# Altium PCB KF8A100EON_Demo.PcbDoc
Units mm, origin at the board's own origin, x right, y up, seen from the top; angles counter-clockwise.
Board outline 55.05 x 80.01 mm, 2 copper layers (Top Layer, Bottom Layer); 33 components, 41 nets, 150 pads, 19 vias.
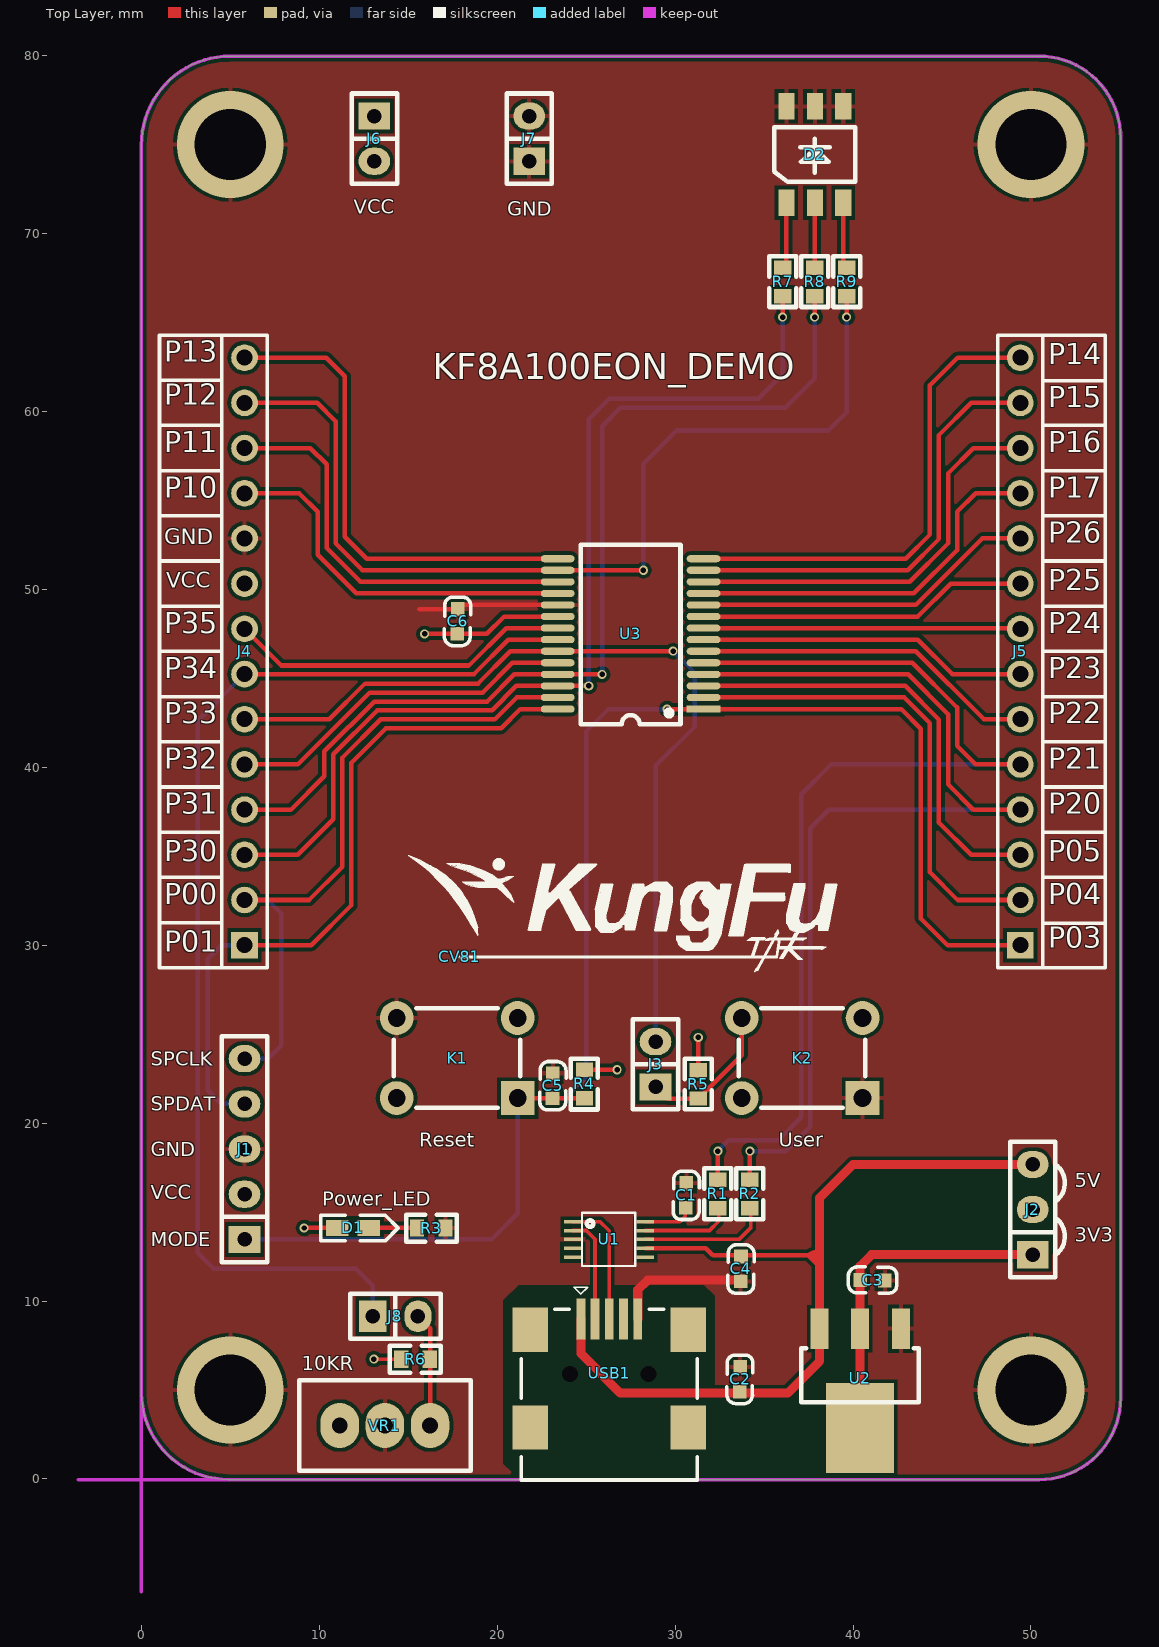
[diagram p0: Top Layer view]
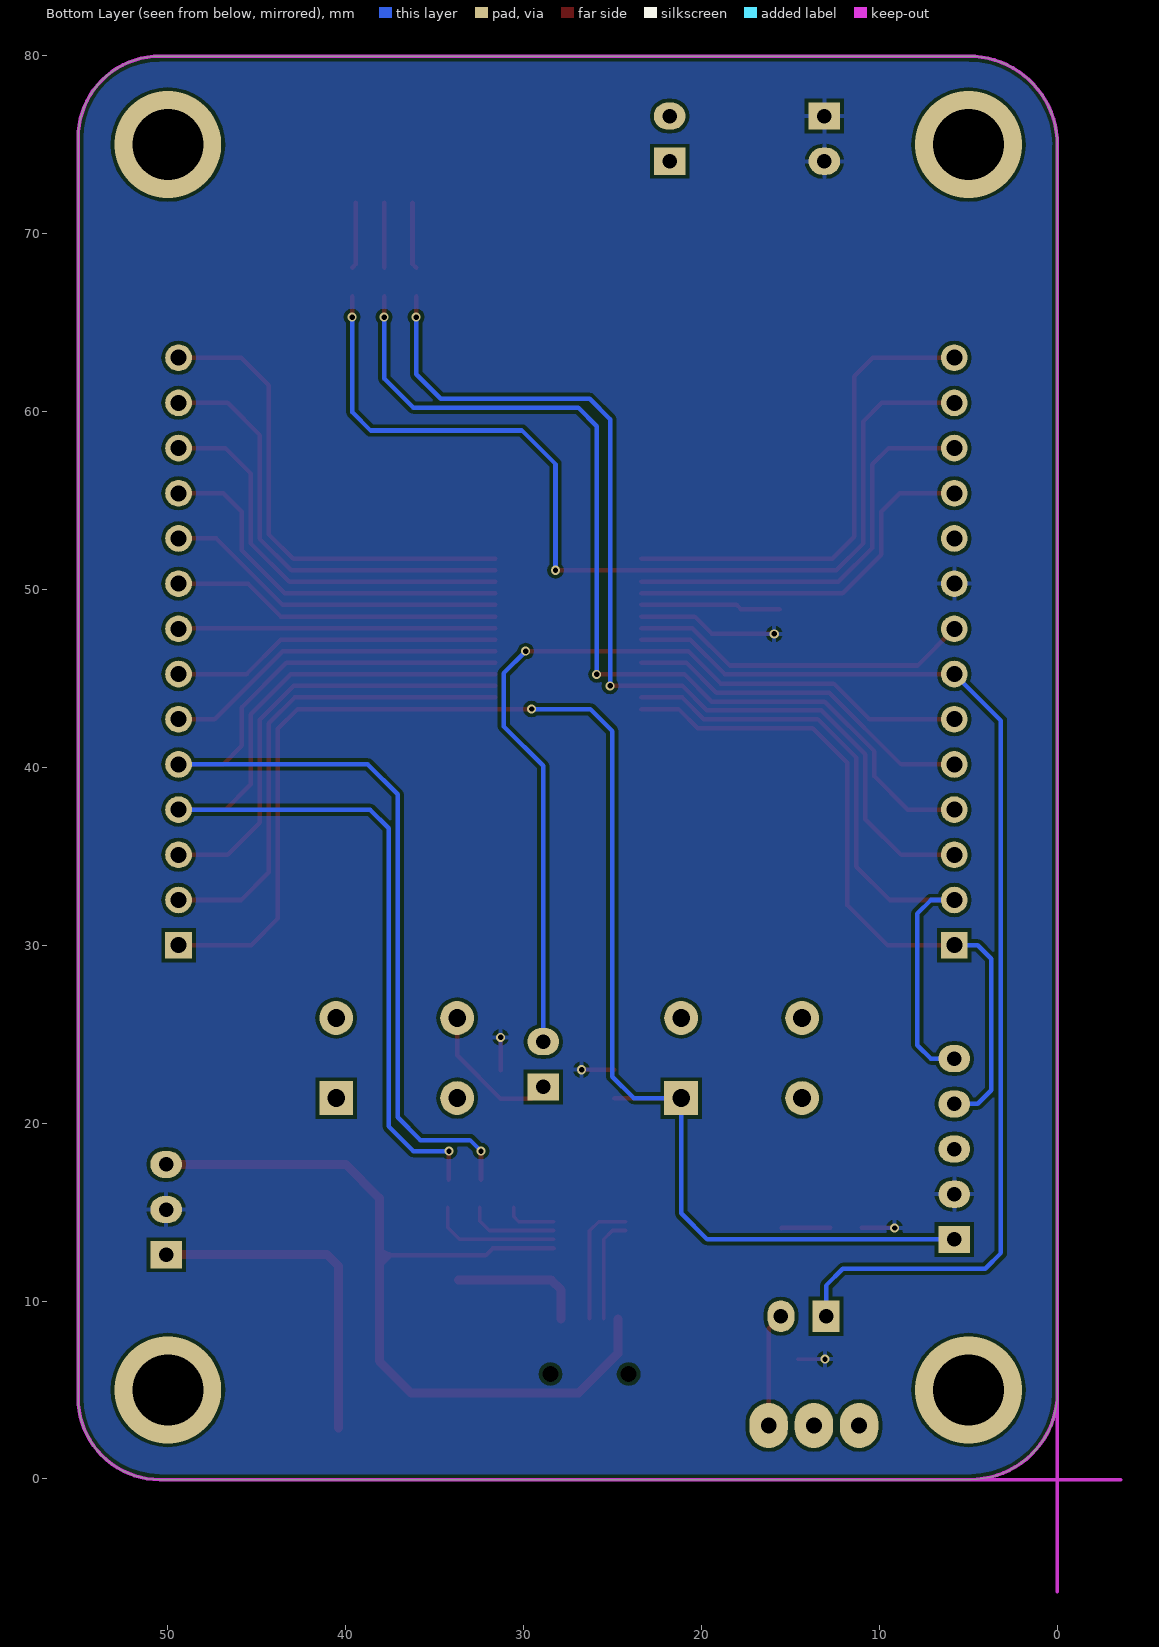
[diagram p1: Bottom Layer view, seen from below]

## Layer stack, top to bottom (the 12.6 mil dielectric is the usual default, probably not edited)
Top Layer: signal copper 0.0356
Dielectric: dielectric 0.32, FR-4, Dk 4.8
Bottom Layer: signal copper 0.0356

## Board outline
4.906,-0.034 cw(c4.906,4.873) 0,4.826 0,74.973 cw(c5,74.973) 5,79.973 50.443,79.973 cw(c50.443,75.369) 55.047,75.369 55.045,75.369 55.039,4.547 55.041,4.547 cw(c50.46,4.547) 50.46,-0.034

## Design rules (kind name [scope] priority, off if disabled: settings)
Clearance [All] p1: gap=0.203
HoleSize [All] p1: absolutevalues=TRUE maxlimit=4 minlimit=0.025 maxpercent=80.000 minpercent=20.000
PolygonConnect [All] p1: connectstyle=Relief reliefconductorwidth=0.254 reliefentries=4 polygonreliefangle="90 Angle"
RoutingVias [All] p1: holewidth=0.711 width=1.27 viastyle="Through Hole" minholewidth=0.305 minwidth=0.508 maxholewidth=4 maxwidth=6
SolderMaskExpansion [All] p1: expansion=0.102
TestPointUsage [All] p1: valid=0 allowmultiple=FALSE
Testpoint [All] p1: side=15 testpointundercomponent=TRUE minsize=1.016 maxsize=2.54 preferedsize=1.524 minholesize=0 maxholesize=1.016 preferedholesize=0.813 testpointgrid=0.025 style=1023 order=0-112345678
Width [All] p1: maxlimit=0.762 minlimit=0.203 preferedwidth=0.254
18 further rules are at their usual default settings.

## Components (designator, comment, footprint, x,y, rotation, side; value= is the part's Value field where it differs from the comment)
C1 "0.1uF" 0603C 30.6,15.238 r90 top
C2 "22uF" 0603C 33.67,6.3 r270 top
C3 "10uF" 0603C 41.8,11.146 r180 top
C4 "10nF" 0603C 33.67,11.1 r90 top
C5 "100nF" 0603C 23.1,21.4 r90 top
C6 "100nF" 0603C 17.8,48.9 r270 top
CV81 "Comment" LOGO 17.907,29.337 r0 top
D1 "LED" LED-0603B 11,14.1 r0 top
D2 "LED-5050" LED-5050W 36.2,71.773 r90 top
J1 "DEBUG" "Pin HDR1X5/2.54mm-S" 5.8,13.462 r180 top locked
J2 "Pin HDR1X3" "Pin HDR1X3/2.54mm-S" 50.1,12.6 r180 top
J3 "Pin HDR1X2" "Pin HDR1X2/2.54mm-S" 28.901,22.037 r180 top
J4 "Pin HDR1X14" "Pin HDR1X14/2.54mm-S" 5.8,30 r90 top
J5 "Pin HDR1X14" "Pin HDR1X14/2.54mm-S" 49.4,30 r90 top locked
J6 "Pin HDR1X2" "Pin HDR1X2/2.54mm-S" 13.1,76.6 r0 top
J7 "Pin HDR1X2" "Pin HDR1X2/2.54mm-S" 21.8,74.06 r180 top
J8 "Pin HDR1X2" "Pin HDR1X2/2.54mm-S" 13.006,9.144 r90 top
K1 "KEY" DIP-6X6X4.3 21.151,21.408 r180 top
K2 "KEY" DIP-6X6X4.3 40.541,21.408 r180 top
R1 "300R" 0603R 32.4,16.818 r270 top
R2 "300R" 0603R 34.2,16.818 r270 top
R3 "470R" 0603R 17.1,14.1 r180 top
R4 "10K" 0603R 24.9,21.4 r90 top
R5 "10K" 0603R 31.301,22.977 r270 top
R6 "10K" 0603R 14.606,6.731 r0 top
R7 "300R" 0603R 36.046,68.079 r270 top
R8 "300R" 0603R 37.846,68.079 r270 top
R9 "300R" 0603R 39.646,68.079 r270 top
U1 "CH340E" MSOP10 24.257,13.462 r0 top
U2 "AMS1117" SOT223 40.4,8.45 r180 top
U3 "KF8FA100EON" SSOP28 27.5,47.498 r180 top locked
USB1 "MINI-USB" USB-MINI-A 24.7,9 r0 top
VR1 "10K" 3296W 13.69,3 r0 top

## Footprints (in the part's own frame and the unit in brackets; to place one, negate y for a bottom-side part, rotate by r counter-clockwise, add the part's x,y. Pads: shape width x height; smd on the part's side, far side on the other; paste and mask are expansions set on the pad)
0603C [mil]
  rect 30x30 smd: 1(0.21,-0.35) 2(55.21,-1.35)
  silkscreen extent -26,-30 81,28, body extent -1,-15 62,17, height 12
0603R [mm]
  rect 0.8x0.965 smd: 1(0,0) 2(1.6,0)
  silkscreen extent -0.64,-0.76 2.21,0.76, body extent -0.04,-0.41 1.56,0.41, height 0.45
3296W [mil]
  oval 85x100 hole 35: 1(-100,0) 2(0,0) 3(100,0)
  silkscreen extent -190,-100 190,100, body extent -188,-94 188,94, height 455
DIP-6X6X4.3 [mm]
  rect 1.9x1.9 hole 1: 1(0,0)
  round 1.9 hole 1: 2(0,-4.5) 3(6.8,-4.5) 4(6.8,0)
  silkscreen extent -0.16,-5.04 6.96,0.54, body extent -0.66,-5.25 7.55,0.75, height 4.25
LED-0603B [mil]
  rect 50x35 smd: A(0,0.26) K(70,0.26)
  silkscreen extent -36,-28 135,28, body extent 4,-15 66,17, height 24
LED-5050W [mm]
  rect 1.5x0.9 smd: 1(-0.038,-0.051) 2(5.372,-0.051) 3(-0.038,-1.651) 4(5.372,-1.651) 5(-0.038,-3.251) 6(5.372,-3.251)
  silkscreen extent 1.14,-3.94 4.19,0.64, body extent -0.03,-4.11 5.37,0.89, height 1.65
LOGO [mm]
  silkscreen extent -2.9,-0.84 21.21,5.71
MSOP10 [mm]
  rect 1x0.2 smd: 1(0,1) 2(0,0.5) 3(0,0) 4(0,-0.5) 5(0,-1) 6(4.064,-1) 7(4.064,-0.5) 8(4.064,0) 9(4.064,0.5) 10(4.064,1)
  silkscreen extent 0.51,-1.5 3.51,1.5
"Pin HDR1X2/2.54mm-S" [mil]
  rect 70x60 hole 32: 1(0,0)
  oval 70x60 hole 32: 2(0,-100)
  silkscreen extent -50,-150 50,50, body extent -50,-150 50,50, height 336
"Pin HDR1X3/2.54mm-S" [mil]
  rect 70x60 hole 32: 1(0,0)
  oval 70x60 hole 32: 2(0,-100) 3(0,-200)
  silkscreen extent -50,-250 50,50, body extent -50,-250 50,50, height 336
"Pin HDR1X5/2.54mm-S" [mil]
  rect 70x60 hole 32: 1(0,0)
  oval 70x60 hole 32: 2(0,-100) 3(0,-200) 4(0,-300) 5(0,-400)
  silkscreen extent -50,-450 50,50, body extent -50,-450 50,50, height 336
"Pin HDR1X14/2.54mm-S" [mm] "Connector; Header; 14 Position"
  rect 1.5x1.5 hole 0.9: 1(0,0)
  round 1.5 hole 0.9: 2(2.54,0) 3(5.08,0) 4(7.62,0) 5(10.16,0) 6(12.7,0) 7(15.24,0) 8(17.78,0) 9(20.32,0) 10(22.86,0) 11(25.4,0) 12(27.94,0) 13(30.48,0) 14(33.02,0)
  silkscreen extent -1.27,-1.27 34.29,1.27, body extent -1.27,-1.27 34.29,1.27, height 7.58
SOT223 [mil]
  rect 40x90 smd: 1(-90,0) 2(0,0) 3(90,0)
  rect 150x200 smd: 2(0,220)
  silkscreen extent -130,43 130,163, body extent -130,-30 126,246, height 65
SSOP28 [mm]
  rect 1.9x0.4 smd: 1(-4.1,4.225)
  oval 1.9x0.4 smd: 2(-4.1,3.575) 3(-4.1,2.925) 4(-4.1,2.275) 5(-4.1,1.625) 6(-4.1,0.975) 7(-4.1,0.325) 8(-4.1,-0.325) 9(-4.1,-0.975) 10(-4.1,-1.625) 11(-4.1,-2.275) 12(-4.1,-2.925) 13(-4.1,-3.575) 14(-4.1,-4.225) 15(4.1,-4.225) 16(4.1,-3.575) 17(4.1,-2.925) 18(4.1,-2.275) 19(4.1,-1.625) 20(4.1,-0.975) 21(4.1,-0.325) 22(4.1,0.325) 23(4.1,0.975) 24(4.1,1.625) 25(4.1,2.275) 26(4.1,2.925) 27(4.1,3.575) 28(4.1,4.225)
  silkscreen extent -2.8,-5 2.8,5.08, body extent -3.85,-5.12 3.85,5.08, height 1.65
USB-MINI-A [mm]
  rect 2x2.5 smd: 0(-2.85,-6.108) 0(-2.85,-0.608) 0(6.05,-6.108) 0(6.05,-0.608)
  rect 0.5x2.3 smd: 1(0,0) 2(0.8,0) 3(1.6,0) 4(2.4,0) 5(3.2,0)
  round 0.6 hole 0.9 unplated: MH1(3.8,-3.108) MH2(-0.6,-3.108)
  silkscreen extent -3.35,-9.06 6.55,1.78, body extent -3.17,-9.04 6.33,0.66, height 3.95

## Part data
C1 C2 C3 C4 C5 C6: library part CAP, "无极性电容"
J1: library part "Pin HDR1X5"
R1 R2 R3 R4 R5 R6 R7 R8 R9: library part RES
U1: "USB to TTL Serial / UART"
U2: "三端稳压芯片"
U3: "SSOP28/TSSOP28"
VR1: library part RESVR

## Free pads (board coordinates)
  round 6 hole 4: 0(5,5) 0(5,75) 0(50,5) 0(50,75)

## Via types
v1: diameter 0.508, hole 0.305, Top Layer to Bottom Layer, 15 vias
v2: diameter 6, hole 4, Top Layer to Bottom Layer, 4 vias

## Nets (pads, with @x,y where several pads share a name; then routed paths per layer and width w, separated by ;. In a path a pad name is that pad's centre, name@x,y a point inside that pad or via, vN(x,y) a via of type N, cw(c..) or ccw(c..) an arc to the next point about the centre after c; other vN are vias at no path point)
ADC: J4.7 J8.1 U3.22 | length 64.3
  Top Layer w0.254: J4.7 18.697,45.24 20.63,47.173 U3.22
  Bottom Layer w0.254: J4.7 3.175,42.615 3.175,12.7 4.064,11.811 12.065,11.811 13.006,10.87 J8.1
GND: C1.2 C2.1 C3.1 C4.1 C5.2 C6.1 D2.2 D2.4 D2.6 J1.3 J4.10 J7.1 J7.2 K1.3 K2.1 pad.0 R3.1 U1.3 U2.1 U3.19 USB1.5 VR1.2 | length 15.5
  Top Layer w0.254: 15.621,48.895 C6.1 18.019,49.123 U3.19
  Top Layer w0.508: USB1.5 27.9,10.626 28.452,11.178 ; 28.461,11.183 C4.1@33.668,11.183
  other v2: 5,5 50,5 5,75 50,75
INT1: J3.2 J4.6 U3.23 | length 49.1
  Top Layer w0.254: J4.6 10.569,42.7 12.573,44.704 18.923,44.704 20.742,46.523 U3.23 v1(29.888,46.523)
  Bottom Layer w0.254: J3.2 28.901,40.077 31.115,42.291 31.115,45.296 v1(29.888,46.523) v1@29.804,46.523
MCU_RX: J5.4 R2.1 U3.4 | length 57.8
  Top Layer w0.254: U3.4 43.098,45.223 45.339,42.982 45.339,39.045 46.764,37.62 J5.4 ; R2.1 v1(34.2,18.43)
  Bottom Layer w0.254: v1(34.2,18.43) 36.21,18.43 37.592,19.812 37.592,36.576 38.636,37.62 J5.4
MCU_TX: J5.5 R1.1 U3.5 | length 59.7
  Top Layer w0.254: U3.5 43.337,45.873 45.847,43.363 45.847,41.204 46.891,40.16 J5.5 ; R1.1 v1(32.4,18.43)
  Bottom Layer w0.254: v1(32.4,18.43) 33.02,19.05 35.814,19.05 37.084,20.32 37.084,38.481 38.763,40.16 J5.5
MODE: C5.1 J1.1 J5.1 K1.1 R4.1 U3.1 | length 86.6
  Top Layer w0.254: K1.1 24.892,21.408 R4.1 ; v1(29.557,43.273) U3.1 42.706,43.273 43.815,42.164 43.815,31.496 45.311,30 J5.1
  Bottom Layer w0.254: J1.1 19.685,13.462 21.151,14.928 K1.1 23.821,21.408 25.019,22.606 25.019,42.037 26.255,43.273 v1(29.557,43.273)
NetC1_1: C1.1 U1.10 | length 2.9
  Top Layer w0.203: U1.10 30.272,14.462 30.57,14.76 C1.1@30.57,15.269
NetD1_K: D1.K R3.2 | length 2.7
  Top Layer w0.254: D1.K 15.493,14.107 R3.2
NetD2_1: D2.1 R7.1 | length 3.7
  Top Layer w0.254: R7.1 36.251,68.284 D2.1
NetD2_3: D2.3 R8.1 | length 3.7
  Top Layer w0.254: R8.1 37.851,68.084 D2.3
NetD2_5: D2.5 R9.1 | length 3.7
  Top Layer w0.254: D2.5 39.451,68.274 R9.1
NetJ3_1: J3.1 K2.3 R5.2 | length 8.2
  Top Layer w0.254: J3.1 29.561,21.377 R5.2 33.741,23.817 K2.3
NetJ8_2: J8.2 R6.2 VR1.3 | length 6.4
  Top Layer w0.254: J8.2 16.23,8.46 VR1.3
NetR1_2: R1.2 U1.9 | length 5.1
  Top Layer w0.203: U1.9 31.931,13.962 32.461,14.492 R1.2@32.461,15.264
NetR2_2: R2.2 U1.8 | length 7.3
  Top Layer w0.203: U1.8 33.59,13.462 34.261,14.133 R2.2@34.261,15.264
P00: J1.5 J4.2 U3.27 | length 38
  Top Layer w0.254: J4.2 9.426,32.54 11.303,34.417 11.303,40.545 13.462,42.704 19.875,42.704 21.095,43.923 U3.27
  Bottom Layer w0.254: J1.5 7.112,23.622 7.874,24.384 7.874,31.75 ; J4.2 7.112,32.54 7.874,31.778
P01: J1.4 J4.1 U3.28 | length 39.9
  Top Layer w0.254: J4.1 9.553,30 11.811,32.258 11.811,40.259 13.748,42.196 20.225,42.196 21.302,43.273 U3.28
  Bottom Layer w0.254: 3.726,29.21 3.726,21.844 4.488,21.082 J1.4 ; 3.726,29.238 4.488,30 J4.1
P04: J5.2 U3.2 | length 27.4
  Top Layer w0.254: U3.2 42.874,43.923 44.323,42.474 44.323,34.092 45.875,32.54 J5.2
P05: J5.3 U3.3 | length 25.1
  Top Layer w0.254: U3.3 42.93,44.573 44.831,42.672 44.831,36.886 46.637,35.08 J5.3
P10: J4.11 U3.18 | length 21.3
  Top Layer w0.254: J4.11 8.862,55.4 9.906,54.356 9.906,51.943 12.076,49.773 U3.18
P11: J4.12 U3.17 | length 23.5
  Top Layer w0.254: J4.12 9.497,57.94 10.414,57.023 10.414,52.324 12.315,50.423 U3.17
P12: J4.13 R9.2 U3.16 | length 55.5
  Top Layer w0.254: J4.13 9.878,60.48 10.922,59.436 10.922,52.578 12.427,51.073 U3.16 v1(28.213,51.073) ; v1(39.646,65.3) R9.2
  Bottom Layer w0.254: v1(28.213,51.073) 28.213,57.042 30.099,58.928 38.608,58.928 39.646,59.966 v1(39.646,65.3)
P13: J4.14 U3.15 | length 27.6
  Top Layer w0.254: J4.14 10.386,63.02 11.43,61.976 11.43,52.959 12.666,51.723 U3.15
P14: J5.14 U3.14 | length 27.4
  Top Layer w0.254: U3.14 42.96,51.723 44.323,53.086 44.323,61.468 45.875,63.02 J5.14
P15: J5.13 U3.13 | length 25.1
  Top Layer w0.254: U3.13 43.072,51.073 44.831,52.832 44.831,58.674 46.637,60.48 J5.13
P16: J5.12 U3.12 | length 23.2
  Top Layer w0.254: U3.12 43.184,50.423 45.339,52.578 45.339,56.515 46.764,57.94 J5.12
P17: J5.11 U3.11 | length 21.4
  Top Layer w0.254: U3.11 43.423,49.773 45.847,52.197 45.847,54.356 46.891,55.4 J5.11
P22: J5.6 U3.6 | length 19.4
  Top Layer w0.254: U3.6 43.535,46.523 47.358,42.7 J5.6
P23: J5.7 U3.7 | length 18.6
  Top Layer w0.254: U3.7 43.647,47.173 45.58,45.24 J5.7
P24: J5.8 U3.8 | length 17.9
  Top Layer w0.254: U3.8 49.357,47.823 J5.8 J5.8@49.357,47.737
P25: J5.9 U3.9 | length 18.6
  Top Layer w0.254: U3.9 43.647,48.473 45.494,50.32 J5.9
P26: J5.10 U3.10 | length 19.3
  Top Layer w0.254: U3.10 43.535,49.123 47.272,52.86 J5.10
P30: J4.3 R7.2 U3.26 | length 56.7
  Top Layer w0.254: J4.3 8.791,35.08 10.795,37.084 10.795,40.735 13.271,43.212 19.717,43.212 21.078,44.573 U3.26 v1(25.146,44.573) ; v1(36.046,65.3) R7.2
  Bottom Layer w0.254: v1(25.146,44.573) 25.146,59.563 26.289,60.706 34.671,60.706 36.046,62.081 v1(36.046,65.3)
P31: J4.4 R8.2 U3.25 | length 55.7
  Top Layer w0.254: J4.4 8.41,37.62 10.287,39.497 10.287,40.894 13.081,43.688 19.431,43.688 20.966,45.223 U3.25 v1(25.897,45.223) ; v1(37.846,65.3) R8.2
  Bottom Layer w0.254: v1(25.897,45.223) 25.897,59.171 26.924,60.198 36.195,60.198 37.846,61.849 v1(37.846,65.3)
P32: J4.5 U3.24 | length 20
  Top Layer w0.254: J4.5 8.791,40.16 12.827,44.196 19.177,44.196 20.854,45.873 U3.24
P35: J4.8 U3.21 | length 19.3
  Top Layer w0.254: J4.8 7.86,45.72 18.415,45.72 20.518,47.823 U3.21
USB_3.3V: C3.2 J2.1 U2.2 | length 19.1
  Top Layer w0.508: U2.2@40.4,2.862 40.4,8.45 40.4,11.956 41.048,12.604 J2.1@50.1,12.604
USB_5V: C2.2 C4.2 J2.3 U1.7 U2.3 USB1.1 | length 49
  Top Layer w0.254: U1.7 31.729,12.962 32.092,12.599 ; 32.131,12.577 37.479,12.577 37.987,12.069
  Top Layer w0.508: USB1.1 24.7,7.056 26.93,4.826 36.324,4.826 38.118,6.62 U2.3@38.118,8.448 ; U2.3 38.114,15.789 40.005,17.68 J2.3
USB_D+: U1.1 USB1.3 | length 7.2
  Top Layer w0.203: U1.1 25.784,14.462 26.3,13.946 USB1.3
USB_D-: U1.2 USB1.2 | length 5.9
  Top Layer w0.203: U1.2 25.014,13.962 25.5,13.476 USB1.2
VCC: C6.2 D1.A J1.2 J2.2 J4.9 J6.1 J6.2 R4.2 R5.1 R6.1 U3.20 | length 15
  Top Layer w0.203: v1(13.067,6.731) R6.1
  Top Layer w0.254: v1(9.154,14.107) D1.A ; v1(15.919,47.498) C6.2 19.42,47.498 20.395,48.473 U3.20 ; R4.2 v1(26.747,23) ; R5.1 v1(31.301,24.823)
pads on no net: K1.2 K1.4 K2.2 K2.4 U1.4 U1.5 U1.6 USB1.0 USB1.4 USB1.MH1 USB1.MH2 VR1.1

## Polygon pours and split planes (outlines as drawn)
GND on Top Layer "Top Layer-No Net" (solid, remove dead copper, pour order 1000): -0.254,81.153 -0.254,1.397 4.191,-3.048 55.753,-3.048 58.674,-0.127 58.674,79.248 56.261,81.661 0.254,81.661 -0.254,81.153
VCC on Bottom Layer "Top Layer-No Net" (solid, remove dead copper, pour order 1001): -0.381,81.026 -0.381,1.27 4.064,-3.175 55.626,-3.175 58.547,-0.254 58.547,79.121 56.134,81.534 0.127,81.534 -0.381,81.026

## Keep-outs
Keep-Out Layer:
  lines w0.2: -3.556,-0.034 50.46,-0.034 ccw(c50.46,4.547) 55.041,4.547 ; 0,-6.35 0,74.973 cw(c5,74.973) 5,79.973 50.443,79.973 cw(c50.443,75.369) 55.047,75.369 ; 0,4.826 ccw(c4.906,4.873) 4.906,-0.034 ; 55.039,4.547 55.045,75.369

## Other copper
Top Layer:
  pour cut-out: 21.209,-0.034 31.589,-0.034 32.258,0.635 32.258,10.287 31.623,10.922 21.209,10.922 20.32,10.033 20.32,0.855
  region net USB_5V: 37.479,12.577 37.479,12.718 37.719,12.831 38.114,12.958 38.114,12.069
  pour cut-out: 51.308,17.68 51.308,12.6 41.048,12.6 40.4,11.952 40.4,0.107 40.259,-0.034 38.114,2.111 38.114,15.789 38.368,15.789 40.259,17.68

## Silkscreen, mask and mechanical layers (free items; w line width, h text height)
Top Overlay:
  lines w0.2: 1.02,31.272 4.53,31.272 ; 1.02,33.812 4.53,33.812 ; 1.02,36.352 4.53,36.352 ; 1.02,38.892 4.53,38.892 ; 1.02,41.432 4.53,41.432 ; 1.02,43.972 4.53,43.972 ; 1.02,46.512 4.53,46.512 ; 1.02,49.052 4.53,49.052 ; 1.02,51.592 4.53,51.592 ; 1.02,54.132 4.53,54.132 ; 1.02,56.672 4.53,56.672 ; 1.02,59.212 4.53,59.212 ; 1.02,61.752 4.53,61.752 ; 4.53,28.732 1.02,28.732 1.02,64.29 4.53,64.29 ; 50.67,28.73 54.18,28.73 54.18,64.29 50.67,64.29 ; 50.67,31.242 54.18,31.242 ; 50.67,33.812 54.145,33.812 ; 50.67,36.352 54.18,36.352 ; 50.67,38.892 54.18,38.892 ; 50.67,41.432 54.18,41.432 ; 50.67,43.972 54.18,43.972 ; 50.67,46.512 54.18,46.512 ; 50.67,49.052 54.18,49.052 ; 50.67,51.592 54.18,51.592 ; 50.67,54.132 54.18,54.132 ; 50.67,56.672 54.18,56.672 ; 50.67,59.212 54.18,59.212 ; 50.67,61.722 54.18,61.722
  lines w0.254: 51.37,14.683 cw(c50.608,13.63) 51.399,12.598 ; 51.37,17.689 cw(c50.608,16.636) 51.399,15.605
  text "VCC" at 11.938,71.12 h0.8
  text "GND" at 20.574,70.993 h0.8
  text "P13" at 1.274,62.387 h2
  text "P14" at 50.97,62.26 h2
  text "KF8A100EON_DEMO" at 16.383,61.341 h2.5
  text "P12" at 1.274,59.974 h2
  text "P15" at 50.97,59.847 h2
  text "P11" at 1.274,57.307 h2
  text "P16" at 50.97,57.307 h2
  text "P10" at 1.274,54.767 h2
  text "P17" at 50.97,54.767 h2
  text "GND" at 1.274,52.227 h1.5
  text "P26" at 50.97,52.227 h2
  text "VCC" at 1.397,49.784 h1.5
  text "P25" at 50.97,49.56 h2
  text "P35" at 1.274,47.147 h2
  text "P24" at 50.97,47.147 h2
  text "P34" at 1.274,44.607 h2
  text "P23" at 50.97,44.607 h2
  text "P33" at 1.274,42.067 h2
  text "P22" at 50.97,42.067 h2
  text "P32" at 1.274,39.527 h2
  text "P21" at 50.97,39.527 h2
  text "P31" at 1.274,36.987 h2
  text "P20" at 50.97,36.987 h2
  text "P30" at 1.274,34.32 h2
  text "P05" at 50.97,34.32 h2
  text "P00" at 1.274,31.907 h2
  text "P04" at 50.97,31.907 h2
  text "P03" at 50.97,29.464 h2
  text "P01" at 1.274,29.24 h2
  text "SPCLK" at 0.535,23.225 h0.8
  text "SPDAT" at 0.535,20.685 h0.8
  text "Reset" at 15.621,18.669 h0.8
  text "User" at 35.814,18.669 h0.8
  text "GND" at 0.535,18.145 h0.8
  text "5V" at 52.451,16.383 h0.8
  text "VCC" at 0.535,15.732 h0.8
  text "Power_LED" at 10.16,15.367 h0.8
  text "3V3" at 52.451,13.335 h0.8
  text "MODE" at 0.535,13.081 h0.8
  text "10KR" at 9.017,6.096 h0.8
